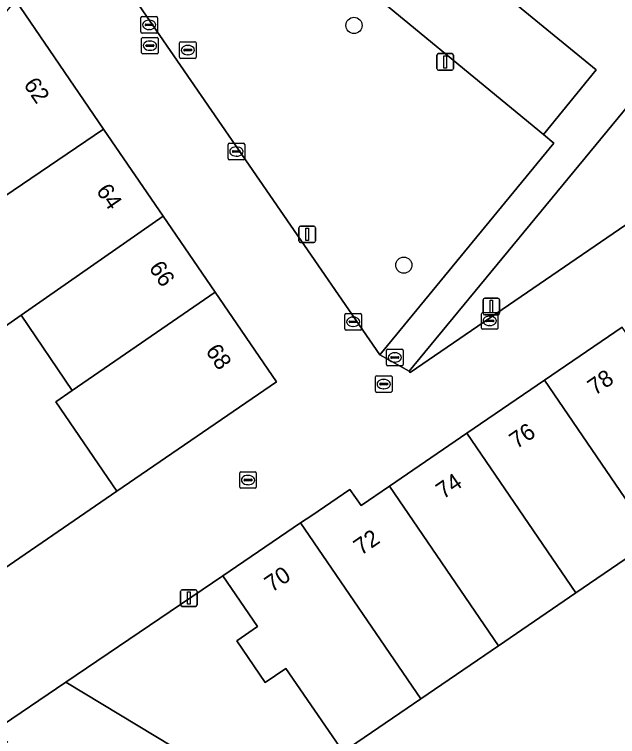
# Model space of a CAD drawing. Extents: x 155275 to 156265, y 382654 to 383635.
# Drawn here: x 155622.23 to 155658.59, y 382967.64 to 383011.16 of the extents above; entities that cross this region are included whole.
import ezdxf

# ---------------------------------------------------------------- set-up
doc = ezdxf.new("R2010")
doc.units = 0
for name, color, linetype in [('IMGEO_Boom', 7, 'Continuous'), ('IMGEO_Erf', 7, 'Continuous'), ('IMGEO_Groenvoorziening', 7, 'Continuous'), ('IMGEO_Hek', 7, 'Continuous'), ('IMGEO_Kolk', 7, 'Continuous'), ('IMGEO_Lichtmast', 7, 'Continuous'), ('IMGEO_Pand', 7, 'Continuous'), ('IMGEO_Pand_nummerreeks', 7, 'Continuous'), ('IMGEO_Parkeervlak_open', 7, 'Continuous'), ('IMGEO_Rioolput', 7, 'Continuous'), ('IMGEO_Voetpad_open', 7, 'Continuous')]:
    doc.layers.add(name, color=color, linetype=linetype)

msp = doc.modelspace()

# ---------------------------------------------------------------- linework, layer by layer
at = {"layer": 'IMGEO_Boom'}
for centre in [(155642.702, 383010.499), (155645.706, 382996.052)]:
    msp.add_circle(centre, 0.489, dxfattribs=at)
at = {"layer": 'IMGEO_Erf'}
msp.add_lwpolyline([(155624.731, 382987.815), (155625.707, 382988.487), (155622.629, 382993.03), (155621.624, 382992.33), (155617.959, 382997.721), (155619.944, 382999.066), (155616.181, 383004.585), (155604.5, 382990.422), (155604.634, 382990.274), (155606.622, 382992.646), (155608.136, 382990.986), (155609.65, 382989.326), (155607.374, 382987.255), (155609.384, 382984.947), (155610.761, 382983.522), (155613.12, 382981.317), (155615.274, 382983.455), (155616.711, 382981.995), (155618.132, 382980.552), (155615.985, 382978.413), (155616.036, 382978.376), (155616.727, 382977.688), (155618.67, 382975.753), (155628.4, 382982.431)], close=True, dxfattribs=at)
msp.add_lwpolyline([(155660.76, 382979.492), (155656.084, 382976.297), (155651.408, 382973.102), (155646.731, 382969.908), (155642.055, 382966.713), (155638.601, 382971.748), (155637.343, 382970.893), (155635.641, 382973.401), (155636.893, 382974.265), (155634.804, 382977.321), (155625.336, 382970.924), (155632.887, 382966.365), (155633.685, 382965.995), (155646.537, 382960.147), (155647.423, 382959.796), (155651.396, 382958.277), (155652.302, 382957.935), (155663.274, 382953.795)], dxfattribs=at)
at = {"layer": 'IMGEO_Groenvoorziening'}
for points in [[(155654.12, 383003.918), (155633.122, 383021.223), (155636.248, 383025.054), (155634.326, 383026.663), (155626.227, 383016.819), (155644.263, 382990.644), (155654.754, 383003.395)], [(155673.776, 383023.305), (155646.029, 382989.662), (155646.092, 382989.591), (155683.577, 383015.26)]]:
    msp.add_lwpolyline(points, close=True, dxfattribs=at)
msp.add_lwpolyline([(155632.887, 382966.365), (155625.336, 382970.924), (155620.978, 382967.979), (155621.831, 382967.301)], dxfattribs=at)
at = {"layer": 'IMGEO_Hek'}
msp.add_lwpolyline([(155625.336, 382970.924), (155632.887, 382966.365), (155638.312, 382963.847), (155641.047, 382962.574), (155647.506, 382959.888), (155647.564, 382959.864)], dxfattribs=at)
at = {"layer": 'IMGEO_Kolk'}
for p, q in [((155629.853, 383010.107), (155629.853, 383010.959)), ((155629.928, 383011.033), (155630.78, 383011.033)), ((155630.854, 383010.959), (155630.854, 383010.107)), ((155630.112, 383010.527), (155630.112, 383010.539)), ((155630.55, 383010.49), (155630.152, 383010.49)), ((155630.155, 383010.576), (155630.553, 383010.576)), ((155630.341, 383010.813), (155630.366, 383010.813)), ((155630.596, 383010.539), (155630.596, 383010.527)), ((155630.364, 383010.253), (155630.339, 383010.253)), ((155630.78, 383010.033), (155629.928, 383010.033)), ((155635.11, 383002.474), (155635.11, 383003.326)), ((155635.185, 383003.4), (155636.037, 383003.4)), ((155635.598, 383003.18), (155635.623, 383003.18)), ((155636.111, 383003.326), (155636.111, 383002.474)), ((155635.369, 383002.894), (155635.369, 383002.906)), ((155635.807, 383002.857), (155635.409, 383002.857)), ((155635.412, 383002.943), (155635.81, 383002.943)), ((155635.853, 383002.906), (155635.853, 383002.894)), ((155636.037, 383002.4), (155635.185, 383002.4)), ((155635.621, 383002.62), (155635.596, 383002.62)), ((155642.226, 382993.14), (155643.078, 382993.14)), ((155650.383, 382992.263), (155650.383, 382993.115)), ((155650.458, 382993.189), (155651.31, 382993.189)), ((155651.384, 382993.115), (155651.384, 382992.263)), ((155642.151, 382992.214), (155642.151, 382993.066)), ((155642.41, 382992.634), (155642.41, 382992.646)), ((155642.453, 382992.683), (155642.851, 382992.683)), ((155642.639, 382992.92), (155642.664, 382992.92)), ((155642.894, 382992.646), (155642.894, 382992.634)), ((155643.152, 382993.066), (155643.152, 382992.214)), ((155650.642, 382992.683), (155650.642, 382992.695)), ((155651.08, 382992.646), (155650.682, 382992.646)), ((155650.685, 382992.732), (155651.083, 382992.732)), ((155650.871, 382992.969), (155650.896, 382992.969)), ((155651.126, 382992.695), (155651.126, 382992.683)), ((155642.848, 382992.597), (155642.45, 382992.597)), ((155642.662, 382992.36), (155642.637, 382992.36)), ((155650.894, 382992.409), (155650.869, 382992.409)), ((155643.078, 382992.14), (155642.226, 382992.14)), ((155651.31, 382992.189), (155650.458, 382992.189)), ((155635.812, 382982.675), (155635.812, 382983.527)), ((155635.887, 382983.601), (155636.739, 382983.601)), ((155636.813, 382983.527), (155636.813, 382982.675)), ((155636.071, 382983.095), (155636.071, 382983.107)), ((155636.114, 382983.144), (155636.512, 382983.144)), ((155636.3, 382983.381), (155636.325, 382983.381)), ((155636.555, 382983.107), (155636.555, 382983.095)), ((155636.509, 382983.058), (155636.111, 382983.058)), ((155636.323, 382982.821), (155636.298, 382982.821)), ((155636.739, 382982.601), (155635.887, 382982.601))]:
    msp.add_line(p, q, dxfattribs=at)
for points in [[(155629.853, 383010.107), (155629.853, 383010.959)], [(155629.928, 383011.033), (155630.78, 383011.033)], [(155630.854, 383010.959), (155630.854, 383010.107)], [(155630.78, 383010.033), (155629.928, 383010.033)], [(155635.11, 383002.474), (155635.11, 383003.326)], [(155635.185, 383003.4), (155636.037, 383003.4)], [(155636.111, 383003.326), (155636.111, 383002.474)], [(155636.037, 383002.4), (155635.185, 383002.4)], [(155642.226, 382993.14), (155643.078, 382993.14)], [(155650.383, 382992.263), (155650.383, 382993.115)], [(155650.458, 382993.189), (155651.31, 382993.189)], [(155651.384, 382993.115), (155651.384, 382992.263)], [(155642.151, 382992.214), (155642.151, 382993.066)], [(155643.152, 382993.066), (155643.152, 382992.214)], [(155643.078, 382992.14), (155642.226, 382992.14)], [(155651.31, 382992.189), (155650.458, 382992.189)], [(155635.812, 382982.675), (155635.812, 382983.527)], [(155635.887, 382983.601), (155636.739, 382983.601)], [(155636.813, 382983.527), (155636.813, 382982.675)], [(155636.739, 382982.601), (155635.887, 382982.601)]]:
    msp.add_lwpolyline(points, dxfattribs=at)
for centre, radius, start, end in [((155629.93, 383010.957), 0.0765, 91.552, 178.448), ((155629.93, 383010.957), 0.0765, 91.552, 178.448), ((155630.778, 383010.957), 0.0765, 1.552, 88.448), ((155630.778, 383010.957), 0.0765, 1.552, 88.448), ((155630.152, 383010.536), 0.0403, 85.8775, 175.7526), ((155630.149, 383010.526), 0.0366, 178.938, 274.7102), ((155630.553, 383010.533), 0.043, 264.8664, 352.4533), ((155630.557, 383010.538), 0.0386, 1.7309, 96.639), ((155629.93, 383010.109), 0.0765, 181.552, 268.448), ((155629.93, 383010.109), 0.0765, 181.552, 268.448), ((155630.778, 383010.109), 0.0765, 271.552, 358.448), ((155630.778, 383010.109), 0.0765, 271.552, 358.448), ((155635.187, 383003.324), 0.0765, 91.552, 178.448), ((155635.187, 383003.324), 0.0765, 91.552, 178.448), ((155636.035, 383003.324), 0.0765, 1.552, 88.448), ((155636.035, 383003.324), 0.0765, 1.552, 88.448), ((155635.409, 383002.903), 0.0403, 85.8775, 175.7526), ((155635.406, 383002.893), 0.0366, 178.938, 274.7102), ((155635.81, 383002.9), 0.043, 264.8664, 352.4533), ((155635.814, 383002.905), 0.0386, 1.7309, 96.639), ((155635.187, 383002.476), 0.0765, 181.552, 268.448), ((155635.187, 383002.476), 0.0765, 181.552, 268.448), ((155636.035, 383002.476), 0.0765, 271.552, 358.448), ((155636.035, 383002.476), 0.0765, 271.552, 358.448), ((155642.228, 382993.064), 0.0765, 91.552, 178.448), ((155642.228, 382993.064), 0.0765, 91.552, 178.448), ((155643.076, 382993.064), 0.0765, 1.552, 88.448), ((155643.076, 382993.064), 0.0765, 1.552, 88.448), ((155650.46, 382993.113), 0.0765, 91.552, 178.448), ((155650.46, 382993.113), 0.0765, 91.552, 178.448), ((155651.308, 382993.113), 0.0765, 1.552, 88.448), ((155651.308, 382993.113), 0.0765, 1.552, 88.448), ((155642.45, 382992.643), 0.0403, 85.8775, 175.7526), ((155642.855, 382992.645), 0.0386, 1.7309, 96.639), ((155650.682, 382992.692), 0.0403, 85.8775, 175.7526), ((155650.679, 382992.682), 0.0366, 178.938, 274.7102), ((155651.083, 382992.689), 0.043, 264.8664, 352.4533), ((155651.087, 382992.694), 0.0386, 1.7309, 96.639), ((155642.228, 382992.216), 0.0765, 181.552, 268.448), ((155642.228, 382992.216), 0.0765, 181.552, 268.448), ((155642.447, 382992.633), 0.0366, 178.938, 274.7102), ((155642.851, 382992.64), 0.043, 264.8664, 352.4533), ((155643.076, 382992.216), 0.0765, 271.552, 358.448), ((155643.076, 382992.216), 0.0765, 271.552, 358.448), ((155650.46, 382992.265), 0.0765, 181.552, 268.448), ((155650.46, 382992.265), 0.0765, 181.552, 268.448), ((155651.308, 382992.265), 0.0765, 271.552, 358.448), ((155651.308, 382992.265), 0.0765, 271.552, 358.448), ((155635.889, 382983.525), 0.0765, 91.552, 178.448), ((155635.889, 382983.525), 0.0765, 91.552, 178.448), ((155636.737, 382983.525), 0.0765, 1.552, 88.448), ((155636.737, 382983.525), 0.0765, 1.552, 88.448), ((155636.111, 382983.104), 0.0403, 85.8775, 175.7526), ((155636.108, 382983.094), 0.0366, 178.938, 274.7102), ((155636.512, 382983.101), 0.043, 264.8664, 352.4533), ((155636.516, 382983.106), 0.0386, 1.7309, 96.639), ((155635.889, 382982.677), 0.0765, 181.552, 268.448), ((155635.889, 382982.677), 0.0765, 181.552, 268.448), ((155636.737, 382982.677), 0.0765, 271.552, 358.448), ((155636.737, 382982.677), 0.0765, 271.552, 358.448)]:
    msp.add_arc(centre, radius, start, end, dxfattribs=at)
for centre, major_axis, ratio, start_param, end_param in [((155630.34, 383010.533), (-0.387, 0.002), 0.722429, 4.712389, 7.853982), ((155630.365, 383010.533), (-0.39, 0.002), 0.717154, 1.570796, 4.712389), ((155635.597, 383002.9), (-0.387, 0.002), 0.722429, 4.712389, 7.853982), ((155635.622, 383002.9), (-0.39, 0.002), 0.717154, 1.570796, 4.712389), ((155642.638, 382992.64), (-0.387, 0.002), 0.722429, 4.712389, 7.853982), ((155642.663, 382992.64), (-0.39, 0.002), 0.717154, 1.570796, 4.712389), ((155650.87, 382992.689), (-0.387, 0.002), 0.722429, 4.712389, 7.853982), ((155650.895, 382992.689), (-0.39, 0.002), 0.717154, 1.570796, 4.712389), ((155636.299, 382983.101), (-0.387, 0.002), 0.722429, 4.712389, 7.853982), ((155636.324, 382983.101), (-0.39, 0.002), 0.717154, 1.570796, 4.712389)]:
    msp.add_ellipse(centre, major_axis=major_axis, ratio=ratio, start_param=start_param, end_param=end_param, dxfattribs=at)
at = {"layer": 'IMGEO_Lichtmast'}
for p, q in [((155647.806, 383008.802), (155648.596, 383008.802)), ((155648.596, 383008.802), (155647.806, 383008.802)), ((155647.706, 383007.902), (155647.706, 383008.702)), ((155647.706, 383008.702), (155647.706, 383007.902)), ((155648.696, 383008.702), (155648.696, 383007.902)), ((155648.696, 383007.902), (155648.696, 383008.702)), ((155648.596, 383007.802), (155647.806, 383007.802)), ((155647.806, 383007.802), (155648.596, 383007.802)), ((155639.385, 382997.508), (155639.385, 382998.308)), ((155639.385, 382998.308), (155639.385, 382997.508)), ((155639.485, 382998.408), (155640.275, 382998.408)), ((155640.275, 382998.408), (155639.485, 382998.408)), ((155640.375, 382998.308), (155640.375, 382997.508)), ((155640.375, 382997.508), (155640.375, 382998.308)), ((155640.275, 382997.408), (155639.485, 382997.408)), ((155639.485, 382997.408), (155640.275, 382997.408)), ((155650.487, 382993.157), (155650.487, 382993.957)), ((155650.487, 382993.957), (155650.487, 382993.157)), ((155650.587, 382994.057), (155651.377, 382994.057)), ((155651.377, 382994.057), (155650.587, 382994.057)), ((155651.477, 382993.957), (155651.477, 382993.157)), ((155651.477, 382993.157), (155651.477, 382993.957)), ((155651.377, 382993.057), (155650.587, 382993.057)), ((155650.587, 382993.057), (155651.377, 382993.057)), ((155632.25, 382975.587), (155632.25, 382976.387)), ((155632.25, 382976.387), (155632.25, 382975.587)), ((155632.35, 382976.487), (155633.14, 382976.487)), ((155633.14, 382976.487), (155632.35, 382976.487)), ((155633.24, 382976.387), (155633.24, 382975.587)), ((155633.24, 382975.587), (155633.24, 382976.387)), ((155633.14, 382975.487), (155632.35, 382975.487)), ((155632.35, 382975.487), (155633.14, 382975.487))]:
    msp.add_line(p, q, dxfattribs=at)
for points in [[(155648.126, 383008.677), (155648.276, 383008.677), (155648.276, 383007.927), (155648.126, 383007.927), (155648.126, 383008.677)], [(155639.805, 382998.283), (155639.955, 382998.283), (155639.955, 382997.533), (155639.805, 382997.533), (155639.805, 382998.283)], [(155650.907, 382993.932), (155651.057, 382993.932), (155651.057, 382993.182), (155650.907, 382993.182), (155650.907, 382993.932)], [(155632.67, 382976.362), (155632.82, 382976.362), (155632.82, 382975.612), (155632.67, 382975.612), (155632.67, 382976.362)]]:
    msp.add_lwpolyline(points, dxfattribs=at)
for centre, start, end in [((155647.806, 383008.702), 90, 180), ((155647.806, 383008.702), 90, 180), ((155648.596, 383008.702), 0, 90), ((155648.596, 383008.702), 360, 90), ((155647.806, 383007.902), 180, 270), ((155647.806, 383007.902), 180, 270), ((155648.596, 383007.902), 270, 0), ((155648.596, 383007.902), 270, 0), ((155639.485, 382998.308), 90, 180), ((155639.485, 382998.308), 90, 180), ((155640.275, 382998.308), 0, 90), ((155640.275, 382998.308), 360, 90), ((155639.485, 382997.508), 180, 270), ((155639.485, 382997.508), 180, 270), ((155640.275, 382997.508), 270, 0), ((155640.275, 382997.508), 270, 0), ((155650.587, 382993.957), 90, 180), ((155650.587, 382993.957), 90, 180), ((155651.377, 382993.957), 0, 90), ((155651.377, 382993.957), 360, 90), ((155650.587, 382993.157), 180, 270), ((155650.587, 382993.157), 180, 270), ((155651.377, 382993.157), 270, 0), ((155651.377, 382993.157), 270, 0), ((155632.35, 382976.387), 90, 180), ((155632.35, 382976.387), 90, 180), ((155633.14, 382976.387), 0, 90), ((155633.14, 382976.387), 360, 90), ((155632.35, 382975.587), 180, 270), ((155632.35, 382975.587), 180, 270), ((155633.14, 382975.587), 270, 0), ((155633.14, 382975.587), 270, 0)]:
    msp.add_arc(centre, 0.1, start, end, dxfattribs=at)
at = {"layer": 'IMGEO_Pand'}
for points in [[(155622.291, 383012.029), (155616.181, 383004.585), (155619.944, 382999.066), (155627.604, 383004.256)], [(155631.197, 382998.998), (155627.604, 383004.256), (155619.944, 382999.066), (155617.959, 382997.721), (155621.624, 382992.33), (155622.629, 382993.03)], [(155634.325, 382994.421), (155631.197, 382998.998), (155622.629, 382993.03), (155625.707, 382988.487)], [(155638.023, 382989.011), (155634.325, 382994.421), (155625.707, 382988.487), (155624.731, 382987.815), (155628.4, 382982.431)], [(155658.86, 382992.312), (155654.184, 382989.117), (155660.76, 382979.492), (155665.436, 382982.686)], [(155654.184, 382989.117), (155649.509, 382985.921), (155656.084, 382976.297), (155660.76, 382979.492)], [(155649.509, 382985.921), (155644.833, 382982.726), (155651.408, 382973.102), (155656.084, 382976.297)], [(155644.833, 382982.726), (155643.128, 382981.561), (155642.445, 382982.532), (155640.154, 382980.97), (155639.485, 382980.514), (155646.731, 382969.908), (155651.408, 382973.102)], [(155639.485, 382980.514), (155634.804, 382977.321), (155636.893, 382974.265), (155635.641, 382973.401), (155637.343, 382970.893), (155638.601, 382971.748), (155642.055, 382966.713), (155646.731, 382969.908)]]:
    msp.add_lwpolyline(points, close=True, dxfattribs=at)
at = {"layer": 'IMGEO_Parkeervlak_open'}
msp.add_lwpolyline([(155636.248, 383025.054), (155633.122, 383021.223), (155654.12, 383003.918), (155657.297, 383007.826)], close=True, dxfattribs=at)
at = {"layer": 'IMGEO_Rioolput'}
for p, q in [((155629.9, 383008.853), (155629.9, 383009.705)), ((155629.975, 383009.779), (155630.827, 383009.779)), ((155630.901, 383009.705), (155630.901, 383008.853)), ((155630.159, 383009.273), (155630.159, 383009.285)), ((155630.597, 383009.236), (155630.199, 383009.236)), ((155630.202, 383009.322), (155630.6, 383009.322)), ((155630.388, 383009.559), (155630.413, 383009.559)), ((155630.643, 383009.285), (155630.643, 383009.273)), ((155632.186, 383008.59), (155632.186, 383009.442)), ((155632.261, 383009.516), (155633.113, 383009.516)), ((155632.674, 383009.296), (155632.699, 383009.296)), ((155633.187, 383009.442), (155633.187, 383008.59)), ((155630.827, 383008.779), (155629.975, 383008.779)), ((155630.411, 383008.999), (155630.386, 383008.999)), ((155632.445, 383009.01), (155632.445, 383009.022)), ((155632.883, 383008.973), (155632.485, 383008.973)), ((155632.488, 383009.059), (155632.886, 383009.059)), ((155632.929, 383009.022), (155632.929, 383009.01)), ((155633.113, 383008.516), (155632.261, 383008.516)), ((155632.697, 383008.736), (155632.672, 383008.736)), ((155644.66, 382990.062), (155644.66, 382990.914)), ((155644.735, 382990.988), (155645.587, 382990.988)), ((155645.661, 382990.914), (155645.661, 382990.062)), ((155644.919, 382990.482), (155644.919, 382990.494)), ((155644.962, 382990.531), (155645.36, 382990.531)), ((155645.148, 382990.768), (155645.173, 382990.768)), ((155645.403, 382990.494), (155645.403, 382990.482)), ((155645.357, 382990.445), (155644.959, 382990.445)), ((155645.171, 382990.208), (155645.146, 382990.208)), ((155645.587, 382989.988), (155644.735, 382989.988)), ((155643.994, 382988.46), (155643.994, 382989.312)), ((155644.069, 382989.386), (155644.921, 382989.386)), ((155644.482, 382989.166), (155644.507, 382989.166)), ((155644.995, 382989.312), (155644.995, 382988.46)), ((155644.253, 382988.88), (155644.253, 382988.892)), ((155644.691, 382988.843), (155644.293, 382988.843)), ((155644.296, 382988.929), (155644.694, 382988.929)), ((155644.737, 382988.892), (155644.737, 382988.88)), ((155644.921, 382988.386), (155644.069, 382988.386)), ((155644.505, 382988.606), (155644.48, 382988.606))]:
    msp.add_line(p, q, dxfattribs=at)
for points in [[(155629.9, 383008.853), (155629.9, 383009.705)], [(155629.975, 383009.779), (155630.827, 383009.779)], [(155630.901, 383009.705), (155630.901, 383008.853)], [(155632.186, 383008.59), (155632.186, 383009.442)], [(155632.261, 383009.516), (155633.113, 383009.516)], [(155633.187, 383009.442), (155633.187, 383008.59)], [(155630.827, 383008.779), (155629.975, 383008.779)], [(155633.113, 383008.516), (155632.261, 383008.516)], [(155644.66, 382990.062), (155644.66, 382990.914)], [(155644.735, 382990.988), (155645.587, 382990.988)], [(155645.661, 382990.914), (155645.661, 382990.062)], [(155645.587, 382989.988), (155644.735, 382989.988)], [(155643.994, 382988.46), (155643.994, 382989.312)], [(155644.069, 382989.386), (155644.921, 382989.386)], [(155644.995, 382989.312), (155644.995, 382988.46)], [(155644.921, 382988.386), (155644.069, 382988.386)]]:
    msp.add_lwpolyline(points, dxfattribs=at)
for centre, radius, start, end in [((155629.977, 383009.703), 0.0765, 91.552, 178.448), ((155629.977, 383009.703), 0.0765, 91.552, 178.448), ((155630.825, 383009.703), 0.0765, 1.552, 88.448), ((155630.825, 383009.703), 0.0765, 1.552, 88.448), ((155630.199, 383009.282), 0.0403, 85.8775, 175.7526), ((155630.196, 383009.272), 0.0366, 178.938, 274.7102), ((155630.6, 383009.279), 0.043, 264.8664, 352.4533), ((155630.604, 383009.284), 0.0386, 1.7309, 96.639), ((155632.263, 383009.44), 0.0765, 91.552, 178.448), ((155632.263, 383009.44), 0.0765, 91.552, 178.448), ((155633.111, 383009.44), 0.0765, 1.552, 88.448), ((155633.111, 383009.44), 0.0765, 1.552, 88.448), ((155629.977, 383008.855), 0.0765, 181.552, 268.448), ((155629.977, 383008.855), 0.0765, 181.552, 268.448), ((155630.825, 383008.855), 0.0765, 271.552, 358.448), ((155630.825, 383008.855), 0.0765, 271.552, 358.448), ((155632.485, 383009.019), 0.0403, 85.8775, 175.7526), ((155632.482, 383009.009), 0.0366, 178.938, 274.7102), ((155632.886, 383009.016), 0.043, 264.8664, 352.4533), ((155632.89, 383009.021), 0.0386, 1.7309, 96.639), ((155632.263, 383008.592), 0.0765, 181.552, 268.448), ((155632.263, 383008.592), 0.0765, 181.552, 268.448), ((155633.111, 383008.592), 0.0765, 271.552, 358.448), ((155633.111, 383008.592), 0.0765, 271.552, 358.448), ((155644.737, 382990.912), 0.0765, 91.552, 178.448), ((155644.737, 382990.912), 0.0765, 91.552, 178.448), ((155645.585, 382990.912), 0.0765, 1.552, 88.448), ((155645.585, 382990.912), 0.0765, 1.552, 88.448), ((155644.959, 382990.491), 0.0403, 85.8775, 175.7526), ((155644.956, 382990.481), 0.0366, 178.938, 274.7102), ((155645.36, 382990.488), 0.043, 264.8664, 352.4533), ((155645.364, 382990.493), 0.0386, 1.7309, 96.639), ((155644.737, 382990.064), 0.0765, 181.552, 268.448), ((155644.737, 382990.064), 0.0765, 181.552, 268.448), ((155645.585, 382990.064), 0.0765, 271.552, 358.448), ((155645.585, 382990.064), 0.0765, 271.552, 358.448), ((155644.071, 382989.31), 0.0765, 91.552, 178.448), ((155644.071, 382989.31), 0.0765, 91.552, 178.448), ((155644.919, 382989.31), 0.0765, 1.552, 88.448), ((155644.919, 382989.31), 0.0765, 1.552, 88.448), ((155644.293, 382988.889), 0.0403, 85.8775, 175.7526), ((155644.29, 382988.879), 0.0366, 178.938, 274.7102), ((155644.694, 382988.886), 0.043, 264.8664, 352.4533), ((155644.698, 382988.891), 0.0386, 1.7309, 96.639), ((155644.071, 382988.462), 0.0765, 181.552, 268.448), ((155644.071, 382988.462), 0.0765, 181.552, 268.448), ((155644.919, 382988.462), 0.0765, 271.552, 358.448), ((155644.919, 382988.462), 0.0765, 271.552, 358.448)]:
    msp.add_arc(centre, radius, start, end, dxfattribs=at)
for centre, major_axis, ratio, start_param, end_param in [((155630.387, 383009.279), (-0.387, 0.002), 0.722429, 4.712389, 7.853982), ((155630.412, 383009.279), (-0.39, 0.002), 0.717154, 1.570796, 4.712389), ((155632.673, 383009.016), (-0.387, 0.002), 0.722429, 4.712389, 7.853982), ((155632.698, 383009.016), (-0.39, 0.002), 0.717154, 1.570796, 4.712389), ((155645.147, 382990.488), (-0.387, 0.002), 0.722429, 4.712389, 7.853982), ((155645.172, 382990.488), (-0.39, 0.002), 0.717154, 1.570796, 4.712389), ((155644.481, 382988.886), (-0.387, 0.002), 0.722429, 4.712389, 7.853982), ((155644.506, 382988.886), (-0.39, 0.002), 0.717154, 1.570796, 4.712389)]:
    msp.add_ellipse(centre, major_axis=major_axis, ratio=ratio, start_param=start_param, end_param=end_param, dxfattribs=at)
at = {"layer": 'IMGEO_Voetpad_open'}
msp.add_lwpolyline([(155673.776, 383023.305), (155683.577, 383015.26), (155685.3, 383016.425), (155675.036, 383024.801), (155651.755, 383043.96), (155649.839, 383045.475), (155646.075, 383040.922), (155647.98, 383039.367), (155665.46, 383024.999), (155667.391, 383023.391), (155659.425, 383013.763), (155657.505, 383015.364), (155640.091, 383029.705), (155638.127, 383031.274), (155634.326, 383026.663), (155636.248, 383025.054), (155657.297, 383007.826), (155654.12, 383003.918), (155654.754, 383003.395), (155644.263, 382990.644), (155646.029, 382989.662)], close=True, dxfattribs=at)
for points in [[(155683.577, 383015.26), (155646.092, 382989.591), (155646.029, 382989.662), (155644.263, 382990.644), (155626.227, 383016.819)], [(155622.291, 383012.029), (155627.604, 383004.256), (155631.197, 382998.998), (155634.325, 382994.421), (155638.023, 382989.011), (155628.4, 382982.431), (155618.67, 382975.753), (155614.688, 382973.02), (155620.978, 382967.979), (155625.336, 382970.924), (155634.804, 382977.321), (155639.485, 382980.514), (155640.154, 382980.97), (155642.445, 382982.532), (155643.128, 382981.561), (155644.833, 382982.726), (155649.509, 382985.921), (155654.184, 382989.117), (155658.86, 382992.312)]]:
    msp.add_lwpolyline(points, dxfattribs=at)

# ---------------------------------------------------------------- texts
at = {"layer": 'IMGEO_Pand_nummerreeks'}
for s, rotation, p in [('62', 304.3486, (155622.747, 383006.932)), ('64', 304.3486, (155627.124, 383000.528)), ('66', 304.3486, (155630.3, 382995.881)), ('68', 304.3486, (155633.721, 382990.875)), ('78', 34.3488, (155657.224, 382988.166)), ('76', 34.3488, (155652.506, 382984.942)), ('74', 34.3488, (155648.082, 382981.919)), ('72', 34.3488, (155643.121, 382978.528)), ('70', 34.2973, (155637.749, 382976.303))]:
    msp.add_text(s, height=1, rotation=rotation, dxfattribs=at).set_placement(p)

doc.saveas('drawing.dxf')
